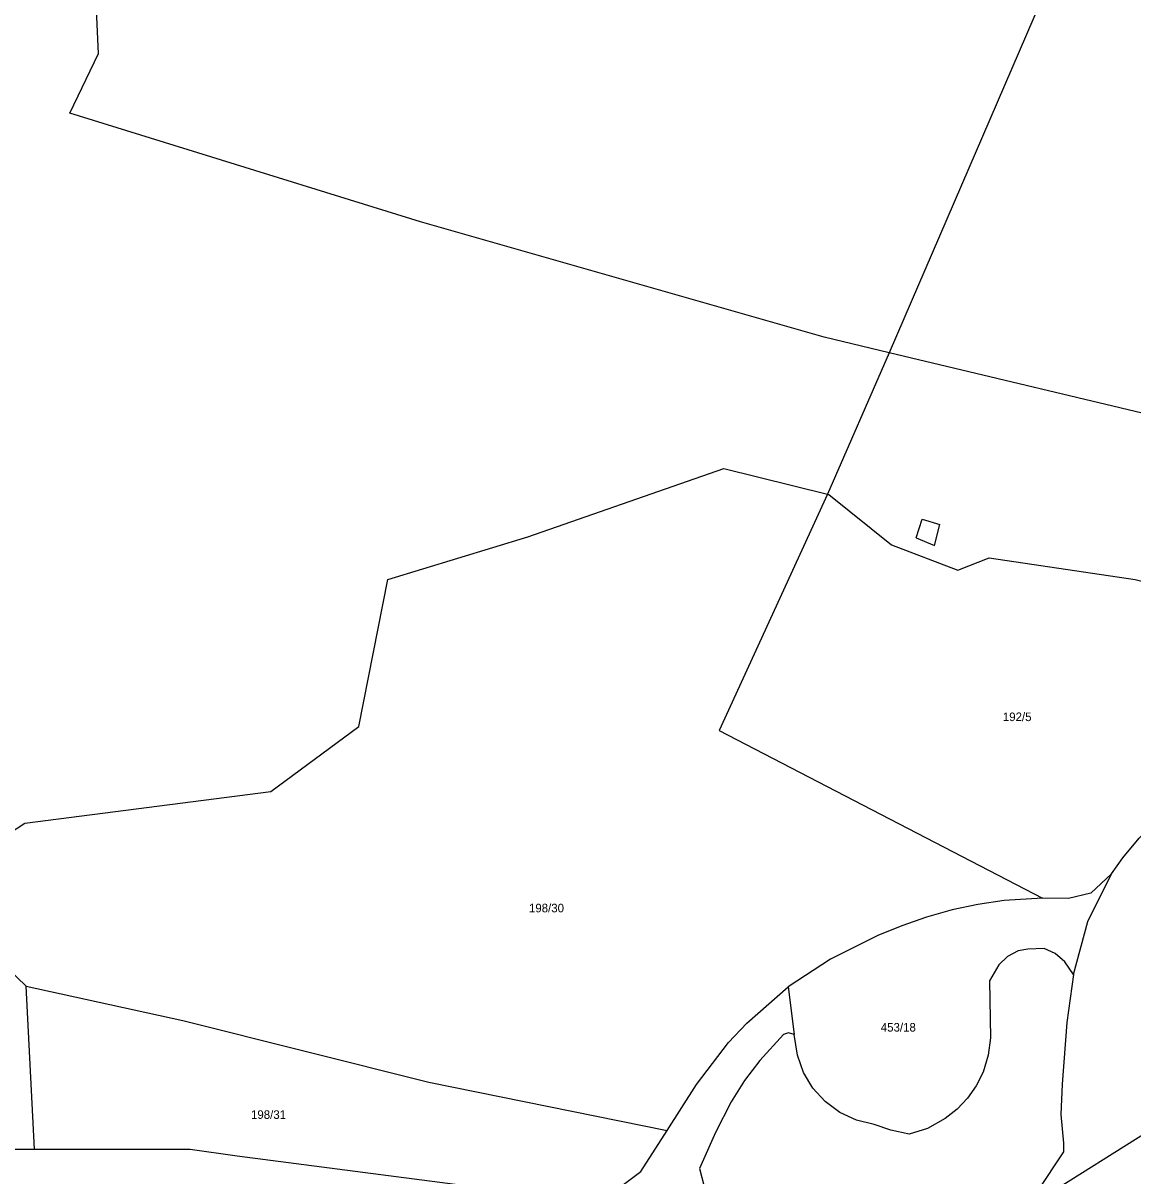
# Model space of a CAD drawing. Extents: x -882150 to -879379, y -1022570 to -1019819.
# Drawn here: x -880677.3 to -880457.2, y -1021005.3 to -1020776.6 of the extents above; entities that cross this region are included whole.
import ezdxf

# ---------------------------------------------------------------- set-up
doc = ezdxf.new("R2010")
doc.units = 0
for name, color, linetype in [('Hranice parcel', 7, 'Continuous'), ('Parcelní čísla', 7, 'Continuous'), ('Vnitřní kresba', 7, 'Continuous')]:
    doc.layers.add(name, color=color, linetype=linetype)

msp = doc.modelspace()

# ---------------------------------------------------------------- linework, layer by layer
at = {"layer": 'Hranice parcel'}
for p, q in [((-880505.51, -1020841.96), (-880517.75, -1020870.05)), ((-880675.05, -1021000), (-880676.73, -1020967.67)), ((-880525.58, -1020967.75), (-880524.39, -1020977.22)), ((-880554.77, -1021004.39), (-880549.58, -1020996.27)), ((-880563.15, -1021010.65), (-880554.77, -1021004.39))]:
    msp.add_line(p, q, dxfattribs=at)
for points in [[(-880360.27, -1020636.82), (-880354.1, -1020637.87), (-880321.84, -1020610.85), (-880294.54, -1020587.99), (-880281.75, -1020603.26), (-880254.56, -1020635.3), (-880265.26, -1020654.96), (-880284.47, -1020671.92), (-880292.9, -1020684.4), (-880298.58, -1020723.73), (-880329.61, -1020741.11), (-880349.9, -1020777.37), (-880372.99, -1020821.6), (-880387.98, -1020873.06), (-880446.75, -1020856.01), (-880505.51, -1020841.96)], [(-880505.51, -1020841.96), (-880518.42, -1020838.87), (-880598.48, -1020816.02), (-880668.07, -1020794.46), (-880662.34, -1020782.6), (-880663.62, -1020755.13), (-880652.38, -1020739.25), (-880665.62, -1020711.65), (-880647.59, -1020705.66), (-880571.11, -1020664.04), (-880510.86, -1020625.14), (-880461.45, -1020618.69), (-880427.21, -1020606.31), (-880394.95, -1020630.96), (-880360.27, -1020636.82)], [(-880360.27, -1020636.82), (-880459.8, -1020735.88), (-880505.51, -1020841.96)], [(-880676.73, -1020967.67), (-880696.89, -1020948.24), (-880676.94, -1020935.31), (-880628.16, -1020929), (-880610.75, -1020916.11), (-880604.98, -1020886.94), (-880577.22, -1020878.49), (-880538.33, -1020864.93), (-880517.75, -1020870.05)], [(-880517.75, -1020870.05), (-880539.25, -1020916.92), (-880475.11, -1020950.17)], [(-880517.75, -1020870.05), (-880517.49, -1020870.11), (-880505.07, -1020880.11), (-880491.9, -1020885.09), (-880485.69, -1020882.64), (-880456.73, -1020886.98), (-880376.21, -1020907.74)], [(-880461.45, -1020945.38), (-880459.21, -1020942.16), (-880455.97, -1020938.25), (-880450.62, -1020932.96), (-880445.34, -1020928.88), (-880438.23, -1020924.03), (-880433.98, -1020921.88), (-880429.27, -1020919.8), (-880422.63, -1020917.62), (-880388.94, -1020910.08), (-880376.21, -1020907.74)], [(-880461.45, -1020945.38), (-880465.55, -1020949.22), (-880469.97, -1020950.26), (-880475.11, -1020950.17)], [(-880469, -1020965.35), (-880466.11, -1020954.81), (-880461.45, -1020945.38)], [(-880833.18, -1020947.96), (-880795.31, -1020965.36), (-880767.59, -1020974.73), (-880722.86, -1020992.68), (-880690, -1021000), (-880675.05, -1021000)], [(-880475.11, -1020950.17), (-880482.7, -1020950.67), (-880487.92, -1020951.44), (-880493.06, -1020952.51), (-880498.1, -1020953.95), (-880503.04, -1020955.68), (-880507.8, -1020957.62), (-880517.18, -1020962.27), (-880525.58, -1020967.75)], [(-880469, -1020965.35), (-880470.69, -1020962.78), (-880472.62, -1020961.13), (-880474.76, -1020960.19), (-880478.06, -1020960.28), (-880479.92, -1020960.66), (-880482.05, -1020961.73), (-880483.81, -1020963.39), (-880485.65, -1020966.59), (-880485.43, -1020977.88), (-880485.88, -1020981.35), (-880486.92, -1020984.7), (-880488.27, -1020987.4), (-880490.02, -1020989.83), (-880492.06, -1020992.04), (-880494.41, -1020993.92), (-880497.94, -1020995.86), (-880501.58, -1020997.03), (-880505.23, -1020996.2), (-880508.53, -1020995.08), (-880512.02, -1020994.23), (-880515.31, -1020992.7), (-880518.23, -1020990.55), (-880520.67, -1020987.87), (-880522.53, -1020984.75), (-880523.74, -1020981.34), (-880524.39, -1020977.22)], [(-880469, -1020965.35), (-880470.29, -1020974.83), (-880471.2, -1020987.07), (-880471.46, -1020993.13), (-880470.95, -1020998.81), (-880470.95, -1021000.53), (-880476.16, -1021008.4)], [(-880676.73, -1020967.67), (-880645.63, -1020974.43), (-880596.86, -1020986.67), (-880549.58, -1020996.27)], [(-880549.58, -1020996.27), (-880543.77, -1020987.16), (-880537.38, -1020978.82), (-880533.77, -1020974.99), (-880525.58, -1020967.75)], [(-880524.39, -1020977.22), (-880525.49, -1020976.89), (-880526.51, -1020977.24), (-880531.17, -1020982.39), (-880534.21, -1020986.35), (-880536.84, -1020990.58), (-880540.01, -1020996.68), (-880543.15, -1021003.81), (-880540.22, -1021015.05)], [(-880675.05, -1021000), (-880644.2, -1021000), (-880634.88, -1021001.29), (-880563.15, -1021010.65)]]:
    msp.add_lwpolyline(points, dxfattribs=at)
at = {"layer": 'Vnitřní kresba'}
for p, q in [((-880500.15, -1020878.72), (-880499.02, -1020874.98)), ((-880499.02, -1020874.98), (-880495.47, -1020876.07)), ((-880496.52, -1020880.22), (-880495.47, -1020876.07)), ((-880500.15, -1020878.72), (-880496.52, -1020880.22)), ((-880497.01, -1021023.34), (-880353.65, -1020933.14))]:
    msp.add_line(p, q, dxfattribs=at)

# ---------------------------------------------------------------- texts
at = {"layer": 'Parcelní čísla'}
for s, p in [('192/5', (-880482.99, -1020915.05)), ('198/30', (-880576.98, -1020952.99)), ('453/18', (-880507.2, -1020976.65)), ('198/31', (-880632.11, -1020993.97))]:
    msp.add_text(s, height=1.7, dxfattribs=at).set_placement(p)

doc.saveas('drawing.dxf')
